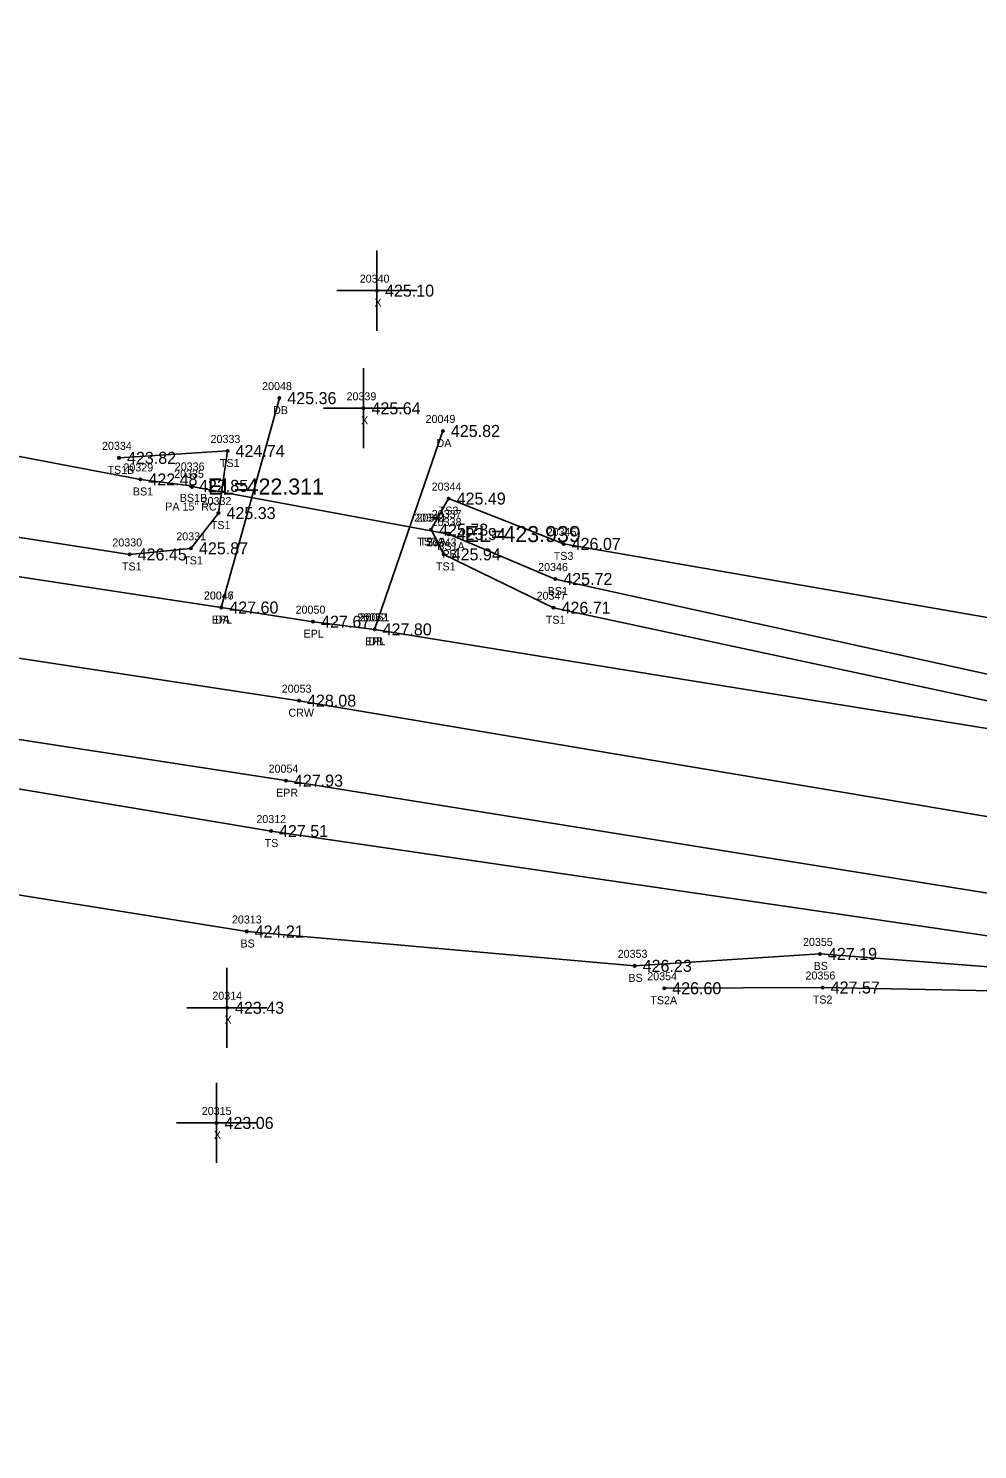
# Model space of a CAD drawing. Extents: x 1613184 to 1614731, y 770859 to 771868.
# Drawn here: x 1614228.7 to 1614347.3, y 771198.3 to 771375.9 of the extents above; entities that cross this region are included whole.
import ezdxf

# ---------------------------------------------------------------- set-up
doc = ezdxf.new("R2010")
doc.units = 0
for name, color, linetype in [('Default', 7, 'Continuous'), ('RD_DTM_BkLn1', 7, 'Continuous'), ('RD_DTM_BkLn2', 7, 'Continuous'), ('RD_DTM_BkLn_txCode', 7, 'Continuous'), ('RD_EX_DR_Pipe_txCode', 7, 'Continuous'), ('RD_EX_Driveway', 7, 'Continuous'), ('RD_EX_Driveway_txCode', 7, 'Continuous'), ('RD_EX_Misc', 7, 'Continuous'), ('RD_EX_Misc_txCode', 7, 'Continuous'), ('RD_EX_Road', 7, 'Continuous'), ('RD_EX_Road_txCode', 7, 'Continuous'), ('RD_EX_TX_Driveway_ELEV', 7, 'Continuous'), ('RD_EX_TX_Misc_ELEV', 7, 'Continuous'), ('RD_EX_TX_Road_ELEV', 7, 'Continuous'), ('RD_HC_Survey_ELEV', 7, 'Continuous'), ('RD_HC_Survey_txCode', 7, 'Continuous'), ('RD_SMD_Locator', 7, 'Continuous'), ('RD_TX_Pipe_ElevEX', 7, 'Continuous')]:
    doc.layers.add(name, color=color, linetype=linetype)

msp = doc.modelspace()

# ---------------------------------------------------------------- linework, layer by layer
at = {"layer": 'Default'}
msp.add_line((1614249.13, 771318.65), (1614281.21, 771312.71), dxfattribs=at)
at = {"layer": 'RD_DTM_BkLn1'}
msp.add_lwpolyline([(1613965.11, 771336.88), (1614064.55, 771323.02), (1614163.88, 771306.86), (1614262.51, 771291.89), (1614361.57, 771275.2), (1614461.76, 771258.77), (1614560.71, 771243.49), (1614660.13, 771228.22)], dxfattribs=at)
at = {"layer": 'RD_DTM_BkLn2'}
for points in [[(1613936.71, 771369.76), (1613950.83, 771373.56), (1613963.82, 771375.88), (1614069.43, 771354.05), (1614168.59, 771333.61), (1614242.69, 771319.53), (1614249.02, 771318.73)], [(1613967.95, 771351.3), (1613989.67, 771350.48), (1614067.09, 771339.84), (1614166.9, 771321.7), (1614241.35, 771310.16), (1614249.01, 771310.92), (1614252.45, 771315.33), (1614253.58, 771323.09), (1614240.02, 771322.23)], [(1613964.19, 771322.73), (1613968.82, 771317.98), (1613995.59, 771312.64), (1614063.18, 771305.5), (1614161.48, 771291.91), (1614259.01, 771275.6), (1614358.23, 771261.08), (1614459.56, 771246.25), (1614559.08, 771230.48), (1614643.28, 771216.31), (1614658.67, 771214.41)], [(1613942.37, 771316.04), (1613958.6, 771307.1), (1613993.85, 771297.11), (1614061.98, 771289.14), (1614161.12, 771278.24), (1614255.97, 771263.05), (1614304.44, 771258.76), (1614327.58, 771260.25), (1614357.86, 771257.94), (1614459.3, 771244.57), (1614558.63, 771228.44), (1614632.25, 771215.15), (1614636.04, 771209.87), (1614639.16, 771208.8), (1614642.36, 771211.01), (1614643.75, 771203.68), (1614650.35, 771198.32), (1614658.52, 771198.65)], [(1614279.01, 771313.26), (1614281.2, 771317.14), (1614295.57, 771311.48), (1614364.56, 771299.51), (1614467.36, 771290.78), (1614524.89, 771285.37), (1614565.75, 771274.12), (1614650.32, 771251.27)], [(1614279.01, 771313.26), (1614280.58, 771310.17), (1614294.3, 771303.5), (1614363.28, 771288.72), (1614464.52, 771272.74), (1614562.89, 771257.17), (1614654.88, 771242.26), (1614663.07, 771241.33)], [(1614281.21, 771312.71), (1614294.52, 771307.09), (1614363.85, 771291.82), (1614464.84, 771274.67), (1614563.17, 771259.04), (1614643.31, 771247.46), (1614652.05, 771248.4), (1614661.41, 771252.06)], [(1614308.13, 771255.96), (1614327.93, 771256.05), (1614357.76, 771255.48), (1614457.77, 771232.22), (1614523.63, 771223.98), (1614557.61, 771219.54), (1614629.42, 771214.32), (1614628.56, 771211.34)]]:
    msp.add_lwpolyline(points, dxfattribs=at)
at = {"layer": 'RD_EX_Driveway'}
for p, q in [((1614252.8, 771303.53), (1614260.05, 771329.69)), ((1614280.48, 771325.59), (1614271.95, 771300.8))]:
    msp.add_line(p, q, dxfattribs=at)
at = {"layer": 'RD_EX_Misc'}
for p, q in [((1614272.25, 771338.12), (1614272.25, 771348.12)), ((1614267.25, 771343.12), (1614277.25, 771343.12)), ((1614270.56, 771323.42), (1614270.56, 771333.42)), ((1614265.56, 771328.42), (1614275.56, 771328.42)), ((1614253.51, 771248.52), (1614253.51, 771258.52)), ((1614248.51, 771253.52), (1614258.51, 771253.52)), ((1614252.2, 771234.13), (1614252.2, 771244.13)), ((1614247.2, 771239.13), (1614257.2, 771239.13))]:
    msp.add_line(p, q, dxfattribs=at)
at = {"layer": 'RD_EX_Road'}
for points in [[(1613966.21, 771346.72), (1614065.91, 771332.61), (1614166, 771316.74), (1614252.8, 771303.53), (1614264.27, 771301.76), (1614271.95, 771300.8), (1614363.43, 771285.99), (1614463.49, 771269.68), (1614562.24, 771253.72), (1614661.91, 771238.32)], [(1613963.41, 771324.71), (1614062.98, 771312.73), (1614162.48, 771297.04), (1614260.87, 771281.9), (1614360.23, 771265.95), (1614460.24, 771249.77), (1614559.17, 771233.87), (1614658.84, 771218.34)]]:
    msp.add_lwpolyline(points, dxfattribs=at)
at = {"layer": 'RD_SMD_Locator'}
for centre, radius in [((1614272.25, 771343.12), 0.15), ((1614260.05, 771329.69), 0.15), ((1614270.56, 771328.42), 0.15), ((1614280.48, 771325.59), 0.15), ((1614253.58, 771323.09), 0.15), ((1614240.02, 771322.23), 0.15), ((1614242.69, 771319.53), 0.15), ((1614249.02, 771318.73), 0.15), ((1614249.13, 771318.65), 0.2), ((1614281.2, 771317.14), 0.15), ((1614252.45, 771315.33), 0.15), ((1614279.01, 771313.26), 0.15), ((1614279.01, 771313.26), 0.15), ((1614281.21, 771312.71), 0.2), ((1614281.21, 771312.71), 0.15), ((1614241.35, 771310.16), 0.15), ((1614249.01, 771310.92), 0.15), ((1614280.58, 771310.17), 0.15), ((1614295.57, 771311.48), 0.15), ((1614294.52, 771307.09), 0.15), ((1614252.8, 771303.53), 0.15), ((1614252.8, 771303.53), 0.15), ((1614294.3, 771303.5), 0.15), ((1614264.27, 771301.76), 0.15), ((1614271.95, 771300.8), 0.15), ((1614271.95, 771300.8), 0.15), ((1614262.51, 771291.89), 0.15), ((1614260.87, 771281.9), 0.15), ((1614259.01, 771275.6), 0.15), ((1614255.97, 771263.05), 0.15), ((1614304.44, 771258.76), 0.15), ((1614327.58, 771260.25), 0.15), ((1614308.13, 771255.96), 0.15), ((1614327.93, 771256.05), 0.15), ((1614253.51, 771253.52), 0.15), ((1614252.2, 771239.13), 0.15)]:
    msp.add_circle(centre, radius, dxfattribs=at)

# ---------------------------------------------------------------- texts
at = {"layer": 'RD_DTM_BkLn_txCode'}
for s, p in [('20333', (1614251.46, 771324.09)), ('20334', (1614237.9, 771323.23)), ('TS1B', (1614238.58, 771320.23)), ('20329', (1614240.57, 771320.53)), ('TS1', (1614252.62, 771321.09)), ('20335', (1614246.91, 771319.73)), ('20344', (1614279.08, 771318.14)), ('BS1', (1614241.75, 771317.53)), ('BS1B', (1614247.61, 771316.73)), ('20332', (1614250.34, 771316.33)), ('TS3', (1614279.96, 771315.14)), ('TS1', (1614251.49, 771313.33)), ('20342', (1614276.89, 771314.26)), ('20341', (1614277.18, 771314.26)), ('20338', (1614279.09, 771313.71)), ('20330', (1614239.19, 771311.16)), ('20331', (1614247.18, 771311.92)), ('TS3A', (1614277.28, 771311.26)), ('TS1A', (1614277.56, 771311.26)), ('20343', (1614278.46, 771311.17)), ('20345', (1614293.45, 771312.48)), ('BS1A', (1614279.78, 771310.71)), ('TS3', (1614294.33, 771309.48)), ('TS1', (1614240.39, 771308.16)), ('TS1', (1614248.05, 771308.92)), ('TS1', (1614279.62, 771308.17)), ('20346', (1614292.38, 771308.09)), ('20347', (1614292.19, 771304.5)), ('BS1', (1614293.57, 771305.09)), ('TS1', (1614293.34, 771301.5)), ('20312', (1614257.18, 771276.6)), ('TS', (1614258.22, 771273.6)), ('20313', (1614254.13, 771264.05)), ('20355', (1614325.47, 771261.25)), ('BS', (1614255.19, 771261.05)), ('20353', (1614302.32, 771259.76)), ('BS', (1614326.8, 771258.25)), ('BS', (1614303.66, 771256.76)), ('20354', (1614306.01, 771256.96)), ('20356', (1614325.79, 771257.05)), ('TS2A', (1614306.4, 771253.96)), ('TS2', (1614326.69, 771254.05))]:
    msp.add_text(s, height=1, dxfattribs=at).set_placement(p)
at = {"layer": 'RD_EX_DR_Pipe_txCode'}
for s, p in [('20336', (1614246.99, 771320.65)), ('PA 15" RC', (1614245.8, 771315.65)), ('20337', (1614279.09, 771314.71)), ('PB', (1614280.43, 771309.71))]:
    msp.add_text(s, height=1, dxfattribs=at).set_placement(p)
at = {"layer": 'RD_EX_Driveway_txCode'}
for s, p in [('20048', (1614257.9, 771330.69)), ('DB', (1614259.27, 771327.69)), ('20049', (1614278.32, 771326.59)), ('DA', (1614279.69, 771323.59)), ('20047', (1614250.64, 771304.53)), ('DA', (1614252.01, 771301.53)), ('20052', (1614269.79, 771301.8)), ('DB', (1614271.17, 771298.8))]:
    msp.add_text(s, height=1, dxfattribs=at).set_placement(p)
at = {"layer": 'RD_EX_Misc_txCode'}
for s, p in [('20340', (1614270.09, 771344.12)), ('X', (1614271.93, 771341.12)), ('20339', (1614268.45, 771329.42)), ('X', (1614270.25, 771326.42)), ('20314', (1614251.68, 771254.52)), ('X', (1614253.2, 771251.52)), ('20315', (1614250.36, 771240.13)), ('X', (1614251.88, 771237.13))]:
    msp.add_text(s, height=1, dxfattribs=at).set_placement(p)
at = {"layer": 'RD_EX_Road_txCode'}
for s, p in [('20046', (1614250.62, 771304.53)), ('20050', (1614262.08, 771302.76)), ('EPL', (1614251.6, 771301.53)), ('20051', (1614270.08, 771301.8)), ('EPL', (1614263.07, 771299.76)), ('EPL', (1614270.75, 771298.8)), ('20054', (1614258.71, 771282.9)), ('EPR', (1614259.64, 771279.9))]:
    msp.add_text(s, height=1, dxfattribs=at).set_placement(p)
at = {"layer": 'RD_EX_TX_Driveway_ELEV'}
for s, p in [('425.36', (1614261.05, 771328.94)), ('425.82', (1614281.48, 771324.84)), ('427.60', (1614253.8, 771302.78)), ('427.80', (1614272.95, 771300.05))]:
    msp.add_text(s, height=1.5, dxfattribs=at).set_placement(p)
at = {"layer": 'RD_EX_TX_Misc_ELEV'}
for s, p in [('425.10', (1614273.25, 771342.37)), ('425.64', (1614271.56, 771327.67)), ('423.82', (1614241.02, 771321.48)), ('424.74', (1614254.58, 771322.34)), ('422.48', (1614243.69, 771318.78)), ('422.85', (1614250.02, 771317.98)), ('425.49', (1614282.2, 771316.39)), ('425.33', (1614253.45, 771314.58)), ('425.73', (1614280.01, 771312.51)), ('425.73', (1614280.01, 771312.51)), ('423.94', (1614282.21, 771311.96)), ('426.07', (1614296.57, 771310.73)), ('426.45', (1614242.35, 771309.41)), ('425.87', (1614250.01, 771310.17)), ('425.94', (1614281.58, 771309.42)), ('425.72', (1614295.52, 771306.34)), ('426.71', (1614295.3, 771302.75)), ('427.51', (1614260.01, 771274.85)), ('424.21', (1614256.97, 771262.3)), ('427.19', (1614328.58, 771259.5)), ('426.23', (1614305.44, 771258.01)), ('426.60', (1614309.13, 771255.21)), ('427.57', (1614328.93, 771255.3)), ('423.43', (1614254.51, 771252.77)), ('423.06', (1614253.2, 771238.38))]:
    msp.add_text(s, height=1.5, dxfattribs=at).set_placement(p)
at = {"layer": 'RD_EX_TX_Road_ELEV'}
for s, p in [('427.60', (1614253.8, 771302.78)), ('427.67', (1614265.27, 771301.01)), ('427.80', (1614272.95, 771300.05)), ('427.93', (1614261.87, 771281.15))]:
    msp.add_text(s, height=1.5, dxfattribs=at).set_placement(p)
at = {"layer": 'RD_HC_Survey_ELEV'}
msp.add_text('428.08', height=1.5, dxfattribs=at).set_placement((1614263.51, 771291.14))
at = {"layer": 'RD_HC_Survey_txCode'}
for s, p in [('20053', (1614260.35, 771292.89)), ('CRW', (1614261.19, 771289.89))]:
    msp.add_text(s, height=1, dxfattribs=at).set_placement(p)
at = {"layer": 'RD_TX_Pipe_ElevEX'}
for s, p in [('EL=422.311', (1614251.13, 771317.65)), ('EL=423.939', (1614283.21, 771311.71))]:
    msp.add_text(s, height=2, dxfattribs=at).set_placement(p)

doc.saveas('drawing.dxf')
